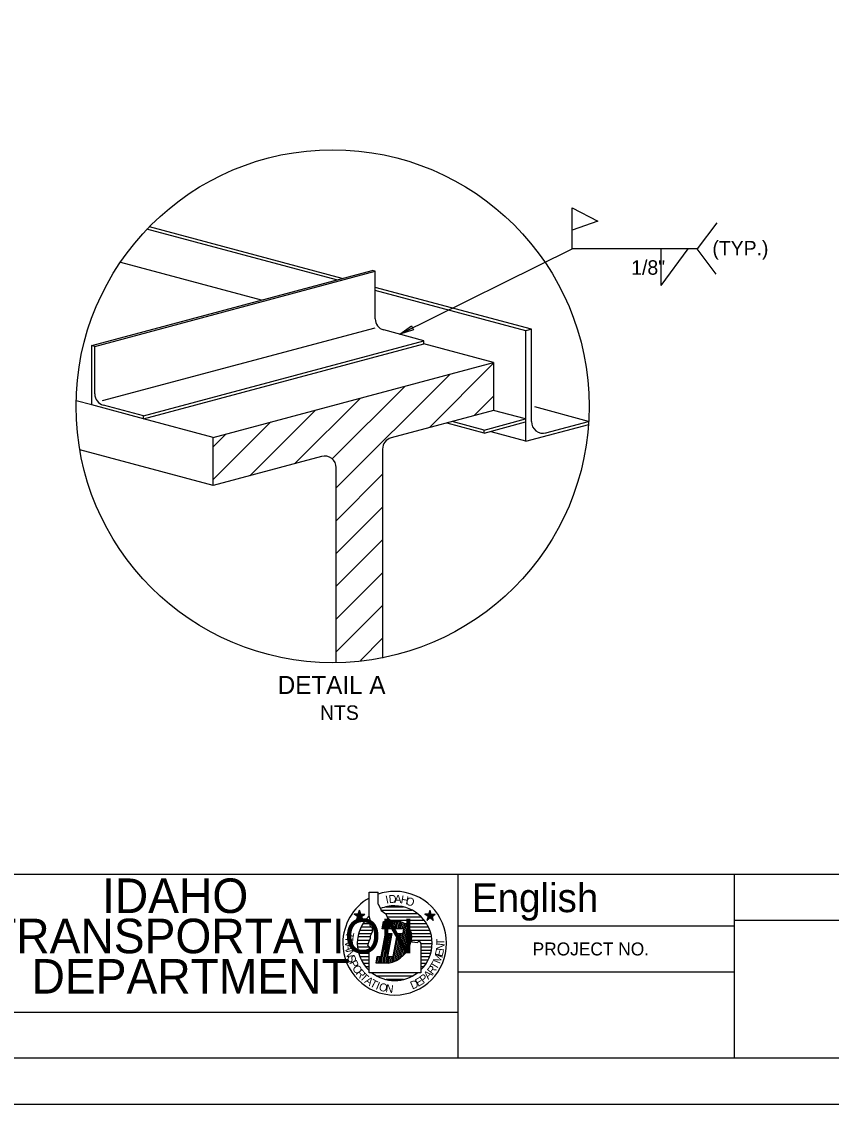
# Model space of a CAD drawing. Extents: x 0 to 34, y 0 to 23.5.
# Drawn here: x 14.51 to 23.3, y 0 to 11.76 of the extents above; entities that cross this region are included whole.
import ezdxf

# ---------------------------------------------------------------- set-up
doc = ezdxf.new("R2010")
doc.units = 0
for name, color, linetype in [('BORDER_ANNO_Cutsheet', 7, 'Continuous'), ('BRDG_ANNO_Anno-Sheet', 7, 'Continuous'), ('BRDG_ANNO_General-Notes', 7, 'Continuous'), ('BRDG_BASE_Obj-Line', 7, 'Continuous'), ('BRDG_BASE_Pattern', 7, 'Continuous')]:
    doc.layers.add(name, color=color, linetype=linetype)

msp = doc.modelspace()

# ---------------------------------------------------------------- linework, layer by layer
at = {"layer": 'BORDER_ANNO_Cutsheet'}
msp.add_lwpolyline([(0, 22), (34, 22), (34, 0), (0, 0)], close=True, dxfattribs=at)
at = {"layer": 'BRDG_ANNO_Anno-Sheet'}
for p, q in [((1.5, 2.5), (19.25, 2.5)), ((19.25, 0.5), (19.25, 2.5)), ((19.25, 2.5), (33.5, 2.5)), ((22.25, 0.5), (22.25, 2.5)), ((18.284, 2.042), (18.284, 2.303)), ((18.284, 2.303), (18.383, 2.303)), ((18.383, 2.173), (18.383, 2.303)), ((18.383, 2.173), (18.409, 2.126)), ((18.409, 2.126), (18.414, 2.105)), ((18.465, 2.144), (18.658, 2.144)), ((18.201, 2.04), (18.122, 2.066)), ((18.166, 2.066), (18.122, 2.066)), ((18.157, 2.04), (18.122, 2.066)), ((18.193, 2.066), (18.144, 1.998)), ((18.157, 2.04), (18.144, 1.998)), ((18.179, 2.024), (18.144, 1.998)), ((18.157, 2.04), (18.237, 2.066)), ((18.166, 2.066), (18.179, 2.107)), ((18.166, 2.066), (18.215, 1.998)), ((18.179, 2.024), (18.179, 2.107)), ((18.193, 2.066), (18.179, 2.107)), ((18.179, 2.024), (18.215, 1.998)), ((18.193, 2.066), (18.237, 2.066)), ((18.201, 2.04), (18.237, 2.066)), ((18.201, 2.04), (18.215, 1.998)), ((18.242, 2.001), (18.294, 2.001)), ((18.274, 2.036), (18.286, 2.036)), ((18.294, 2.006), (18.284, 2.042)), ((18.294, 1.975), (18.294, 2.006)), ((18.414, 2.105), (18.466, 2.069)), ((18.417, 2.108), (18.751, 2.108)), ((18.465, 2.072), (18.807, 2.072)), ((18.466, 2.069), (18.482, 2.027)), ((18.479, 2.036), (18.851, 2.036)), ((18.482, 2.027), (18.534, 1.986)), ((18.516, 2.001), (18.883, 2.001)), ((18.968, 2.04), (18.888, 2.066)), ((18.924, 2.04), (18.888, 2.066)), ((18.932, 2.066), (18.888, 2.066)), ((18.959, 2.066), (18.91, 1.998)), ((18.924, 2.04), (18.91, 1.998)), ((18.946, 2.024), (18.91, 1.998)), ((18.924, 2.04), (19.002, 2.066)), ((18.932, 2.066), (18.946, 2.107)), ((18.932, 2.066), (18.981, 1.998)), ((18.946, 2.024), (18.946, 2.107)), ((18.959, 2.066), (18.946, 2.107)), ((18.946, 2.024), (18.981, 1.998)), ((18.959, 2.066), (19.002, 2.066)), ((18.968, 2.04), (19.002, 2.066)), ((18.968, 2.04), (18.981, 1.998)), ((22.25, 2), (30.25, 2)), ((18.181, 1.892), (18.319, 1.892)), ((18.197, 1.928), (18.298, 1.928)), ((18.217, 1.964), (18.293, 1.964)), ((18.294, 1.949), (18.294, 1.975)), ((18.3, 1.928), (18.294, 1.949)), ((18.321, 1.917), (18.3, 1.928)), ((18.321, 1.891), (18.321, 1.917)), ((18.321, 1.876), (18.321, 1.891)), ((18.425, 1.907), (18.441, 1.986)), ((18.661, 1.907), (18.425, 1.907)), ((18.439, 1.907), (18.454, 1.986)), ((18.441, 1.986), (18.613, 1.986)), ((18.455, 1.907), (18.47, 1.986)), ((18.471, 1.907), (18.486, 1.986)), ((18.487, 1.907), (18.502, 1.986)), ((18.502, 1.907), (18.517, 1.986)), ((18.519, 1.907), (18.533, 1.986)), ((18.534, 1.907), (18.549, 1.986)), ((18.551, 1.907), (18.565, 1.986)), ((18.566, 1.907), (18.581, 1.986)), ((18.582, 1.907), (18.597, 1.986)), ((18.598, 1.907), (18.613, 1.986)), ((18.599, 1.574), (18.672, 1.962)), ((18.614, 1.907), (18.628, 1.981)), ((18.617, 1.586), (18.686, 1.952)), ((18.63, 1.907), (18.643, 1.977)), ((18.636, 1.601), (18.699, 1.939)), ((18.646, 1.907), (18.657, 1.97)), ((18.652, 1.855), (18.661, 1.907)), ((18.656, 1.619), (18.712, 1.924)), ((18.669, 1.964), (18.907, 1.964)), ((18.676, 1.64), (18.725, 1.906)), ((18.697, 1.669), (18.737, 1.882)), ((18.71, 1.928), (18.927, 1.928)), ((18.732, 1.892), (18.943, 1.892)), ((19.25, 1.938), (22.25, 1.938)), ((18.157, 1.784), (18.291, 1.784)), ((18.162, 1.821), (18.298, 1.821)), ((18.171, 1.856), (18.311, 1.856)), ((18.279, 1.751), (18.284, 1.772)), ((18.284, 1.772), (18.3, 1.803)), ((18.3, 1.829), (18.31, 1.85)), ((18.3, 1.803), (18.3, 1.829)), ((18.31, 1.85), (18.321, 1.876)), ((18.414, 1.605), (18.461, 1.855)), ((18.416, 1.532), (18.477, 1.855)), ((18.433, 1.532), (18.493, 1.855)), ((18.448, 1.532), (18.509, 1.855)), ((18.461, 1.855), (18.53, 1.855)), ((18.464, 1.532), (18.525, 1.855)), ((18.53, 1.855), (18.483, 1.605)), ((18.544, 1.605), (18.591, 1.855)), ((18.547, 1.547), (18.604, 1.855)), ((18.564, 1.555), (18.62, 1.855)), ((18.581, 1.563), (18.636, 1.855)), ((18.591, 1.855), (18.652, 1.855)), ((18.722, 1.718), (18.746, 1.845)), ((18.741, 1.777), (18.748, 1.766)), ((18.742, 1.784), (18.968, 1.784)), ((18.744, 1.856), (18.954, 1.856)), ((18.747, 1.821), (18.962, 1.821)), ((18.748, 1.766), (18.779, 1.761)), ((18.811, 1.756), (18.826, 1.777)), ((18.826, 1.777), (18.847, 1.746)), ((18.156, 1.748), (18.277, 1.748)), ((18.158, 1.712), (18.281, 1.712)), ((18.163, 1.676), (18.298, 1.676)), ((18.269, 1.725), (18.279, 1.751)), ((18.284, 1.709), (18.269, 1.725)), ((18.294, 1.694), (18.284, 1.709)), ((18.284, 1.652), (18.3, 1.667)), ((18.284, 1.427), (18.284, 1.652)), ((18.3, 1.683), (18.294, 1.694)), ((18.3, 1.667), (18.3, 1.683)), ((18.779, 1.761), (18.811, 1.756)), ((18.845, 1.748), (18.969, 1.748)), ((18.847, 1.746), (18.847, 1.427)), ((18.847, 1.676), (18.962, 1.676)), ((18.848, 1.712), (18.967, 1.712)), ((18.171, 1.641), (18.284, 1.641)), ((18.184, 1.604), (18.282, 1.604)), ((18.199, 1.568), (18.282, 1.568)), ((18.22, 1.532), (18.283, 1.532)), ((18.359, 1.532), (18.373, 1.605)), ((18.492, 1.532), (18.359, 1.532)), ((18.369, 1.532), (18.383, 1.605)), ((18.373, 1.605), (18.414, 1.605)), ((18.385, 1.532), (18.399, 1.605)), ((18.401, 1.532), (18.414, 1.605)), ((18.48, 1.532), (18.494, 1.605)), ((18.483, 1.605), (18.544, 1.605)), ((18.496, 1.532), (18.51, 1.605)), ((18.513, 1.537), (18.526, 1.605)), ((18.53, 1.542), (18.541, 1.605)), ((18.847, 1.641), (18.954, 1.641)), ((18.847, 1.604), (18.941, 1.604)), ((18.847, 1.568), (18.925, 1.568)), ((18.847, 1.532), (18.905, 1.532)), ((18.246, 1.496), (18.282, 1.496)), ((18.277, 1.461), (18.284, 1.461)), ((18.847, 1.427), (18.284, 1.427)), ((18.847, 1.496), (18.88, 1.496)), ((19.25, 1.438), (22.25, 1.438)), ((18.751, 1.391), (18.372, 1.391)), ((18.659, 1.356), (18.468, 1.356)), ((14, 1), (19.25, 1))]:
    msp.add_line(p, q, dxfattribs=at)
msp.add_lwpolyline([(1.5, 21.5), (33.5, 21.5), (33.5, 0.5), (1.5, 0.5)], close=True, dxfattribs=at)
for centre, radius, start, end in [((18.562, 1.75), 0.563, 119.6331, 180), ((18.562, 1.75), 0.563, 90, 108.596), ((18.562, 1.75), 0.563, 0, 90), ((18.562, 1.75), 0.406, 90, 112.1452), ((18.562, 1.75), 0.406, 0, 90), ((18.562, 1.75), 0.406, 133.1926, 180), ((18.583, 1.824), 0.164, 343.4981, 79.7362), ((18.435, 1.838), 0.312, 280.6479, 348.7719), ((18.562, 1.75), 0.563, 180, 270), ((18.562, 1.75), 0.406, 180.2644, 226.7946), ((18.562, 1.75), 0.563, 270, 0), ((18.562, 1.75), 0.406, 314.427, 0), ((18.562, 1.75), 0.406, 232.5658, 270), ((18.562, 1.75), 0.406, 270, 307.4536)]:
    msp.add_arc(centre, radius, start, end, dxfattribs=at)
at = {"layer": 'BRDG_ANNO_General-Notes'}
for p, q in [((20.488, 9.289), (20.488, 9.734)), ((22.058, 9.573), (21.847, 9.289)), ((18.619, 8.365), (20.488, 9.289)), ((21.847, 9.289), (20.488, 9.289)), ((21.453, 8.893), (21.453, 9.289)), ((21.453, 8.893), (21.749, 9.289)), ((22.052, 9.016), (21.847, 9.289)), ((18.619, 8.365), (18.744, 8.455)), ((18.766, 8.409), (18.619, 8.365)), ((18.744, 8.455), (18.766, 8.409))]:
    msp.add_line(p, q, dxfattribs=at)
msp.add_lwpolyline([(20.488, 9.734), (20.767, 9.591), (20.489, 9.492)], close=True, dxfattribs=at)
at = {"layer": 'BRDG_BASE_Obj-Line'}
for p, q in [((17.991, 8.967), (15.9, 9.528)), ((17.93, 8.952), (15.872, 9.503)), ((15.274, 8.239), (18.318, 9.055)), ((17.115, 8.733), (15.588, 9.142)), ((18.349, 9.047), (18.318, 9.055)), ((15.306, 8.231), (18.349, 9.047)), ((18.349, 8.532), (18.349, 9.047)), ((20.046, 8.417), (18.35, 8.871)), ((19.985, 8.401), (18.35, 8.839)), ((15.391, 7.642), (18.349, 8.434)), ((18.879, 8.292), (18.443, 8.409)), ((20.046, 8.417), (19.985, 8.401)), ((19.985, 7.201), (19.985, 8.401)), ((20.046, 7.415), (20.046, 8.417)), ((15.274, 7.595), (15.274, 8.239)), ((15.306, 8.231), (15.274, 8.239)), ((15.306, 7.716), (15.306, 8.231)), ((15.834, 7.478), (18.879, 8.292)), ((15.834, 7.444), (18.879, 8.26)), ((18.879, 8.26), (18.879, 8.292)), ((19.636, 8.057), (18.879, 8.26)), ((16.591, 7.241), (19.636, 8.057)), ((19.636, 8.057), (19.636, 7.536)), ((15.274, 7.595), (15.103, 7.64)), ((15.834, 7.444), (15.274, 7.595)), ((15.834, 7.478), (15.399, 7.594)), ((19.636, 7.536), (18.524, 7.238)), ((19.983, 7.443), (19.636, 7.536)), ((20.667, 7.417), (20.083, 7.573)), ((15.834, 7.444), (15.834, 7.478)), ((16.591, 7.241), (15.834, 7.444)), ((19.533, 7.322), (19.187, 7.415)), ((19.533, 7.322), (19.983, 7.443)), ((19.533, 7.29), (19.983, 7.41)), ((20.204, 7.293), (20.667, 7.417)), ((19.533, 7.29), (19.13, 7.397)), ((19.533, 7.29), (19.533, 7.322)), ((19.985, 7.201), (19.608, 7.302)), ((19.985, 7.201), (20.669, 7.384)), ((16.591, 6.72), (16.591, 7.241)), ((16.591, 6.72), (15.142, 7.109)), ((18.43, 7.116), (18.43, 4.845)), ((17.768, 7.036), (16.591, 6.72)), ((17.926, 4.796), (17.926, 6.914))]:
    msp.add_line(p, q, dxfattribs=at)
msp.add_circle((17.888, 7.581), 2.785, dxfattribs=at)
for centre, start, end in [((18.476, 8.531), 180, 255.0209), ((15.431, 7.715), 180, 254.9847), ((20.172, 7.414), 180, 284.9948), ((18.556, 7.116), 105.0091, 180), ((17.801, 6.914), 0, 104.989)]:
    msp.add_arc(centre, 0.126, start, end, dxfattribs=at)
at = {"layer": 'BRDG_BASE_Pattern'}
for p, q in [((18.938, 7.349), (19.636, 8.047)), ((17.926, 6.694), (19.163, 7.931)), ((17.888, 7.012), (18.676, 7.8)), ((17.478, 6.958), (18.19, 7.67)), ((19.424, 7.48), (19.636, 7.69)), ((16.99, 6.827), (17.703, 7.54)), ((16.591, 6.784), (17.217, 7.41)), ((16.591, 7.14), (16.73, 7.279)), ((17.926, 6.338), (18.43, 6.842)), ((17.926, 5.982), (18.43, 6.486)), ((17.926, 5.626), (18.43, 6.129)), ((17.926, 5.269), (18.43, 5.773)), ((17.926, 4.913), (18.43, 5.417)), ((18.189, 4.819), (18.43, 5.061))]:
    msp.add_line(p, q, dxfattribs=at)

# ---------------------------------------------------------------- texts
at = {"layer": 'BRDG_ANNO_Anno-Sheet'}
for s, height, p in [('IDAHO', 0.375, (15.384, 2.078)), ('English', 0.3125, (19.401, 2.087)), ('TRANSPORTATION', 0.375, (14.147, 1.641)), ('PROJECT NO.', 0.14062, (20.059, 1.617)), ('DEPARTMENT', 0.375, (14.619, 1.203))]:
    msp.add_text(s, height=height, dxfattribs=at).set_placement(p)
for s, rotation, p in [('I', 11.9519, (18.472, 2.178)), ('D', 5.2118, (18.501, 2.184)), ('A', 357.8718, (18.557, 2.188)), ('H', 349.6318, (18.622, 2.184)), ('O', 342.1917, (18.674, 2.173)), ('R', 266.0275, (18.026, 1.807)), ('T', 259.4265, (18.038, 1.876)), ('T', 90.4926, (19.102, 1.729)), ('A', 273.764, (18.023, 1.741)), ('N', 280.3758, (18.029, 1.671)), ('E', 75.6105, (19.079, 1.597)), ('N', 83.1932, (19.095, 1.663)), ('S', 287.9279, (18.043, 1.604)), ('P', 295.4976, (18.066, 1.541)), ('T', 59.0362, (19.014, 1.455)), ('M', 67.7139, (19.051, 1.521)), ('O', 302.6446, (18.096, 1.48)), ('R', 309.9079, (18.134, 1.422)), ('T', 317.1211, (18.177, 1.371)), ('P', 37.6656, (18.873, 1.309)), ('A', 45, (18.926, 1.351)), ('R', 52.3344, (18.974, 1.401)), ('A', 324.6375, (18.228, 1.326)), ('T', 331.7503, (18.284, 1.287)), ('I', 337.0213, (18.349, 1.254)), ('O', 343.3287, (18.383, 1.241)), ('N', 351.6598, (18.459, 1.22)), ('D', 22.9887, (18.753, 1.246)), ('E', 30.5476, (18.816, 1.274))]:
    msp.add_text(s, height=0.0869, rotation=rotation, dxfattribs=at).set_placement(p)
at = {"layer": 'BRDG_ANNO_General-Notes'}
for s, height, p in [('(TYP.)', 0.1574, (22.011, 9.219)), ('1/8"', 0.1574, (21.13, 9.009)), ('DETAIL A', 0.1968, (17.292, 4.456)), ('NTS', 0.1575, (17.751, 4.175))]:
    msp.add_text(s, height=height, dxfattribs=at).set_placement(p)

doc.saveas('drawing.dxf')
